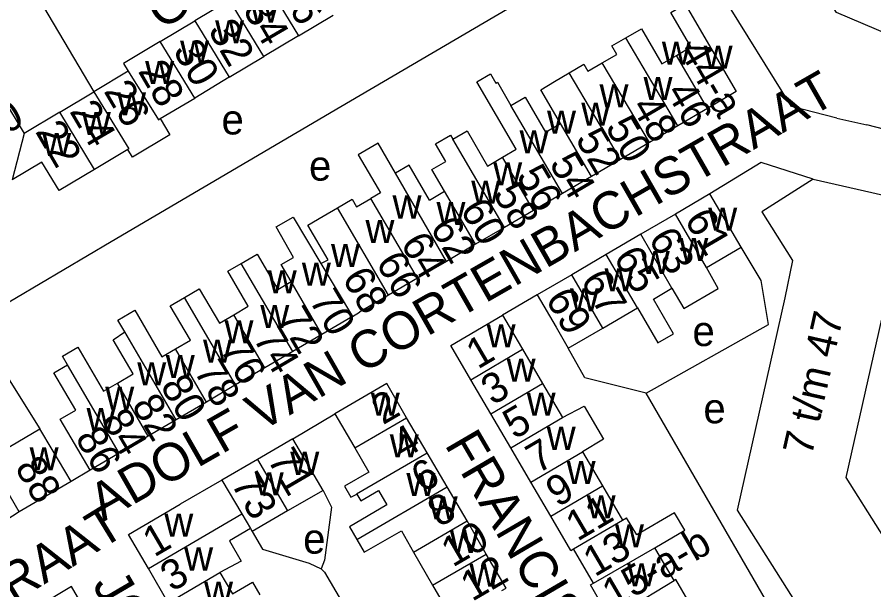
# Model space of a CAD drawing. Extents: x 161141 to 163125, y 381621 to 383200.
# Drawn here: x 162238.7 to 162353, y 382805.6 to 382882 of the extents above; entities that cross this region are included whole.
import ezdxf

# ---------------------------------------------------------------- set-up
doc = ezdxf.new("R2010")
doc.units = 0
for name, color, linetype in [('BLT_Basislijn', 7, 'Continuous'), ('BLT_Bebouwing', 7, 'Continuous'), ('BLT_Centroide', 7, 'Continuous'), ('BLT_Huisnummer', 7, 'Continuous'), ('BLT_Huisnummer_ tussenligend', 7, 'Continuous'), ('BLT_Huisnummer_reeks', 7, 'Continuous'), ('BLT_Onderverdeling_panden', 7, 'Continuous'), ('BLT_Straatnaam', 7, 'Continuous')]:
    doc.layers.add(name, color=color, linetype=linetype)

msp = doc.modelspace()

# ---------------------------------------------------------------- linework, layer by layer
at = {"layer": 'BLT_Basislijn'}
for p, q in [((162281.91, 382870.08), (162321.91, 382893.57)), ((162348.08, 382868.52), (162352.05, 382867.64)), ((162362.91, 382864.89), (162352.05, 382867.64)), ((162308.09, 382844.98), (162303.47, 382842.27)), ((162232.45, 382841.89), (162241.77, 382827.12)), ((162275.49, 382825.8), (162281.12, 382829.13)), ((162248.46, 382821.59), (162245.91, 382820.07)), ((162239.01, 382816.04), (162236.3, 382814.31))]:
    msp.add_line(p, q, dxfattribs=at)
for points in [[(162212.8, 382927.28), (162217.79, 382919.66), (162219.94, 382921.05), (162248.97, 382872.07)], [(162348.08, 382868.52), (162342.04, 382870.09), (162323.43, 382900), (162318.95, 382907.23), (162315.23, 382913.69)], [(162372.69, 382875.58), (162355.12, 382879.62), (162348.02, 382882.61), (162336.91, 382900), (162330.9, 382909.8)], [(162232.45, 382841.89), (162235.42, 382842.77), (162251.28, 382852.08), (162281.91, 382870.08)], [(162344.9, 382860.39), (162337.96, 382862.62), (162331.14, 382858.44)], [(162322.62, 382831.85), (162338.96, 382841.02), (162337.96, 382846.88), (162335.3, 382851.32)], [(162322.62, 382831.85), (162314.44, 382833.92), (162312.24, 382837.86)], [(162369.74, 382797.76), (162350.51, 382784.33), (162341.18, 382799.83), (162322.62, 382831.85)], [(162279.53, 382818.89), (162280.67, 382816.67), (162279.74, 382809.59), (162279.3, 382808.43)], [(162270.06, 382813.44), (162271.46, 382811.07), (162277.7, 382809.19), (162279.3, 382808.43)], [(162279.3, 382808.43), (162279.72, 382807.99), (162287.16, 382795.35), (162288.1, 382793.34), (162291.63, 382787.7), (162296.43, 382779.23), (162324.59, 382730.81)]]:
    msp.add_lwpolyline(points, dxfattribs=at)
at = {"layer": 'BLT_Bebouwing'}
for p, q in [((162267.04, 382884.3), (162262.43, 382881.53)), ((162276.26, 382879.51), (162280.88, 382882.27)), ((162257.82, 382878.76), (162262.43, 382881.53)), ((162276.26, 382879.51), (162271.64, 382876.75)), ((162267.02, 382873.99), (162271.64, 382876.75)), ((162253.52, 382874.8), (162248.97, 382872.07)), ((162267.02, 382873.99), (162262.41, 382871.23)), ((162244.4, 382869.32), (162248.97, 382872.07)), ((162236.75, 382871.31), (162239.66, 382866.48)), ((162257.82, 382868.5), (162262.41, 382871.23)), ((162330.81, 382869.83), (162326.84, 382867.51)), ((162244.4, 382869.32), (162239.66, 382866.48)), ((162326.84, 382867.51), (162323.08, 382865.3)), ((162323.08, 382865.3), (162319.21, 382863.04)), ((162253.51, 382864.37), (162249.04, 382861.7)), ((162319.21, 382863.04), (162315.34, 382860.78)), ((162315.34, 382860.78), (162311.48, 382858.51)), ((162311.48, 382858.51), (162307.61, 382856.24)), ((162331.14, 382858.44), (162326.53, 382855.75)), ((162307.61, 382856.24), (162303.74, 382853.98)), ((162326.53, 382855.75), (162321.92, 382853.06)), ((162303.74, 382853.98), (162299.88, 382851.72)), ((162321.92, 382853.06), (162317.31, 382850.36)), ((162299.88, 382851.72), (162296.01, 382849.45)), ((162330.69, 382848.63), (162335.3, 382851.32)), ((162317.31, 382850.36), (162312.7, 382847.67)), ((162296.01, 382849.45), (162292.15, 382847.19)), ((162292.15, 382847.19), (162288.28, 382844.92)), ((162312.7, 382847.67), (162308.09, 382844.98)), ((162288.28, 382844.92), (162284.41, 382842.66)), ((162283.44, 382842.08), (162284.41, 382842.66)), ((162316.86, 382840.55), (162321.47, 382843.24)), ((162283.44, 382842.08), (162279.39, 382839.71)), ((162251.53, 382838.98), (162253.1, 382840.03)), ((162312.24, 382837.86), (162316.86, 382840.55)), ((162279.39, 382839.71), (162275.5, 382837.43)), ((162306.14, 382837.72), (162308.81, 382833.16)), ((162275.5, 382837.43), (162271.76, 382835.24)), ((162271.76, 382835.24), (162267.87, 382832.97)), ((162301.9, 382829.11), (162299.24, 382833.67)), ((162308.81, 382833.16), (162311.48, 382828.61)), ((162267.87, 382832.97), (162263.99, 382830.69)), ((162263.99, 382830.69), (162259.95, 382828.33)), ((162293.41, 382823.93), (162290.68, 382828.6)), ((162304.57, 382824.56), (162301.9, 382829.11)), ((162259.95, 382828.33), (162256.22, 382826.14)), ((162256.22, 382826.14), (162252.34, 382823.87)), ((162275.49, 382825.8), (162270.77, 382823.04)), ((162252.34, 382823.87), (162248.46, 382821.59)), ((162296.07, 382819.38), (162293.41, 382823.93)), ((162307.24, 382820.01), (162304.57, 382824.56)), ((162314.14, 382824.05), (162316.81, 382819.5)), ((162270.77, 382823.04), (162266.05, 382820.29)), ((162245.91, 382820.07), (162239.01, 382816.04)), ((162266.05, 382820.29), (162260.49, 382817.05)), ((162298.74, 382814.85), (162296.07, 382819.38)), ((162309.91, 382815.45), (162307.24, 382820.01)), ((162316.81, 382819.5), (162319.48, 382814.95)), ((162279.53, 382818.89), (162274.8, 382816.16)), ((162274.8, 382816.16), (162270.06, 382813.44)), ((162301.3, 382810.42), (162298.74, 382814.85)), ((162312.58, 382810.9), (162309.91, 382815.45)), ((162319.48, 382814.95), (162320.01, 382815.26)), ((162321.4, 382812.96), (162320.01, 382815.26)), ((162269.84, 382813.81), (162270.06, 382813.44)), ((162291.58, 382810.67), (162294.15, 382806.26)), ((162303.95, 382805.87), (162301.3, 382810.42)), ((162312.58, 382810.9), (162312.93, 382811.11)), ((162315.6, 382806.55), (162312.93, 382811.11)), ((162326.37, 382806.89), (162323.79, 382811.23)), ((162258.88, 382803.92), (162256.23, 382808.47)), ((162294.15, 382806.26), (162296.8, 382801.71)), ((162303.4, 382805.55), (162303.95, 382805.87)), ((162315.2, 382806.32), (162315.6, 382806.55)), ((162317.86, 382801.76), (162315.2, 382806.32))]:
    msp.add_line(p, q, dxfattribs=at)
for points in [[(162326.67, 382876.91), (162328.61, 382878.05), (162325.92, 382882.64), (162327.85, 382883.73)], [(162327.85, 382883.73), (162334.66, 382872.09), (162330.81, 382869.83)], [(162319.94, 382879.27), (162322, 382880.47), (162324.74, 382875.78), (162326.67, 382876.91)], [(162257.82, 382878.76), (162252.91, 382875.83), (162253.52, 382874.8)], [(162316.76, 382875.91), (162318.72, 382877.04), (162318.07, 382878.17), (162319.94, 382879.27)], [(162312.37, 382874.59), (162314.32, 382875.73), (162314.87, 382874.79), (162316.76, 382875.91)], [(162303.47, 382863.32), (162305.3, 382864.39), (162300.04, 382873.38), (162301.85, 382874.45), (162302.57, 382873.22), (162302.79, 382873.34), (162304.59, 382870.22)], [(162311.2, 382867.85), (162308.57, 382872.33), (162310.41, 382873.44), (162312.37, 382874.59)], [(162304.59, 382870.22), (162306.49, 382871.34), (162309.21, 382866.68), (162311.2, 382867.85)], [(162257.82, 382868.5), (162259.11, 382866.33), (162254.11, 382863.36), (162253.51, 382864.37)], [(162295.73, 382858.8), (162294.04, 382861.69), (162295.9, 382862.78), (162294.53, 382865.11), (162296.54, 382866.28), (162296.86, 382865.73)], [(162296.86, 382865.73), (162298.76, 382866.84), (162301.49, 382862.16), (162303.47, 382863.32)], [(162289.21, 382861.22), (162286.88, 382865.19), (162284.22, 382863.64), (162286.87, 382859.12), (162287.19, 382858.57), (162285.91, 382857.83)], [(162249.04, 382861.7), (162244.34, 382858.88), (162242.01, 382862.69), (162238.06, 382860.31)], [(162293.73, 382857.62), (162291.01, 382862.27), (162289.21, 382861.22)], [(162344.9, 382860.39), (162338.05, 382856.06), (162342.15, 382849.54), (162341.14, 382844.6), (162334.78, 382816.27)], [(162344.9, 382860.39), (162361.15, 382856.7), (162361.15, 382856.7)], [(162293.73, 382857.62), (162295.73, 382858.8)], [(162335.3, 382851.32), (162333.66, 382854.12), (162331.14, 382858.44)], [(162281.45, 382856.59), (162283.4, 382857.73), (162284, 382856.7), (162285.91, 382857.83)], [(162279.24, 382849.16), (162280.22, 382849.65), (162277.51, 382854.28), (162279.53, 382855.46), (162281.45, 382856.59)], [(162381.56, 382852.12), (162380.23, 382846.22), (162383.74, 382845.43), (162376.75, 382814.45), (162362.5, 382805.44), (162358.29, 382806.4), (162349.3, 382820.62), (162356.31, 382851.62), (162359.83, 382850.83), (162361.15, 382856.7)], [(162275.26, 382846.75), (162273.93, 382849.02), (162275.57, 382849.98), (162273.26, 382854.04), (162275.56, 382855.35), (162279.24, 382849.16)], [(162268.62, 382849.18), (162270.73, 382850.41), (162273.48, 382845.71), (162275.26, 382846.75)], [(162267.61, 382842.31), (162269.55, 382843.45), (162266.82, 382848.12), (162268.62, 382849.18)], [(162326.08, 382845.86), (162327.66, 382843.16), (162332.22, 382845.82), (162330.69, 382848.63)], [(162334.78, 382816.27), (162352.31, 382788.59), (162381.03, 382806.89), (162388.22, 382805.26), (162394.4, 382832.58), (162398.03, 382848.41)], [(162261.04, 382844.63), (162263.02, 382845.79), (162265.71, 382841.2), (162267.61, 382842.31)], [(162321.47, 382843.24), (162324.21, 382838.59), (162326.29, 382839.8), (162323.6, 382844.41), (162326.08, 382845.86)], [(162259.84, 382837.78), (162261.84, 382838.95), (162259.15, 382843.53), (162261.04, 382844.63)], [(162308.09, 382844.98), (162310.61, 382840.66), (162312.24, 382837.86)], [(162253.1, 382840.03), (162252.17, 382841.61), (162254.41, 382842.92)], [(162254.41, 382842.92), (162258.04, 382836.73), (162259.84, 382837.78)], [(162299.24, 382833.67), (162296.57, 382838.22), (162303.47, 382842.27)], [(162303.47, 382842.27), (162306, 382837.95), (162306.14, 382837.72)], [(162252.1, 382833.22), (162254.18, 382834.44), (162251.53, 382838.98)], [(162245.44, 382835.65), (162244.76, 382836.8), (162246.82, 382838.01), (162250.26, 382832.14), (162252.1, 382833.22)], [(162244.46, 382828.39), (162246.56, 382829.62), (162243.64, 382834.6), (162245.44, 382835.65)], [(162290.68, 382828.6), (162288.02, 382833.16), (162281.12, 382829.13)], [(162311.48, 382828.61), (162314.38, 382830.12), (162316.96, 382825.74), (162314.14, 382824.05)], [(162281.12, 382829.13), (162283.64, 382824.81), (162283.77, 382824.58)], [(162248.46, 382821.59), (162245.93, 382825.91), (162244.46, 382828.39)], [(162239.01, 382816.04), (162236.49, 382820.36), (162234.88, 382823.09), (162241.77, 382827.12)], [(162245.91, 382820.07), (162243.38, 382824.38), (162241.77, 382827.12)], [(162279.53, 382818.89), (162278.02, 382821.49), (162275.49, 382825.8)], [(162283.77, 382824.58), (162285.66, 382821.35), (162282.41, 382819.46), (162283.26, 382818.01), (162284.04, 382818.4)], [(162284.04, 382818.4), (162284.55, 382817.52), (162286.91, 382818.9), (162288.04, 382816.96), (162283.07, 382814.05), (162284.05, 382812.37)], [(162256.23, 382808.47), (162253.58, 382813.03), (162260.49, 382817.05)], [(162323.79, 382811.23), (162327.8, 382813.58), (162326.43, 382815.92), (162321.4, 382812.97)], [(162269.84, 382813.81), (162267.04, 382812.17), (162268.63, 382809.46), (162265.78, 382807.96)], [(162284.05, 382812.37), (162285.03, 382810.68), (162290, 382813.5), (162291.58, 382810.67)], [(162265.78, 382807.96), (162267.44, 382805.09), (162270.12, 382806.65), (162271.09, 382804.96)], [(162329.32, 382802.35), (162326.58, 382807.02), (162326.37, 382806.89)], [(162250.78, 382797.8), (162245.97, 382806.08), (162241.38, 382803.35)]]:
    msp.add_lwpolyline(points, dxfattribs=at)
at = {"layer": 'BLT_Onderverdeling_panden'}
for p, q in [((162271.66, 382887.07), (162276.26, 382879.51)), ((162271.64, 382876.75), (162267.04, 382884.3)), ((162262.43, 382881.53), (162267.02, 382873.99)), ((162262.41, 382871.23), (162257.82, 382878.76)), ((162326.84, 382867.51), (162319.94, 382879.27)), ((162330.81, 382869.83), (162326.67, 382876.91)), ((162323.08, 382865.3), (162316.76, 382875.91)), ((162319.21, 382863.04), (162312.37, 382874.59)), ((162311.48, 382858.51), (162304.59, 382870.22)), ((162249.04, 382861.7), (162244.4, 382869.32)), ((162315.34, 382860.78), (162311.2, 382867.85)), ((162239.66, 382866.48), (162238.06, 382860.31)), ((162303.74, 382853.98), (162296.86, 382865.73)), ((162307.61, 382856.24), (162303.47, 382863.32)), ((162296.01, 382849.45), (162289.21, 382861.22)), ((162299.88, 382851.72), (162295.73, 382858.8)), ((162292.15, 382847.19), (162285.91, 382857.83)), ((162288.28, 382844.92), (162281.45, 382856.59)), ((162330.69, 382848.63), (162326.53, 382855.75)), ((162326.08, 382845.86), (162321.92, 382853.06)), ((162321.47, 382843.24), (162317.31, 382850.36)), ((162275.5, 382837.43), (162268.62, 382849.18)), ((162279.24, 382849.16), (162283.44, 382842.08)), ((162279.39, 382839.71), (162275.26, 382846.75)), ((162316.86, 382840.55), (162312.7, 382847.67)), ((162267.87, 382832.97), (162261.04, 382844.63)), ((162271.76, 382835.24), (162267.61, 382842.31)), ((162259.95, 382828.33), (162253.1, 382840.03)), ((162263.99, 382830.69), (162259.84, 382837.78)), ((162299.24, 382833.67), (162306.14, 382837.72)), ((162252.34, 382823.87), (162245.44, 382835.65)), ((162256.22, 382826.14), (162252.1, 382833.22)), ((162301.9, 382829.11), (162308.81, 382833.16)), ((162283.77, 382824.58), (162290.68, 382828.6)), ((162304.57, 382824.56), (162311.48, 382828.61)), ((162307.24, 382820.01), (162314.14, 382824.05)), ((162270.77, 382823.04), (162274.8, 382816.16)), ((162284.05, 382812.37), (162296.07, 382819.38)), ((162309.91, 382815.45), (162316.81, 382819.5)), ((162256.23, 382808.47), (162268.7, 382815.77)), ((162268.7, 382815.77), (162269.84, 382813.81)), ((162291.58, 382810.67), (162298.74, 382814.85)), ((162312.93, 382811.11), (162319.48, 382814.95)), ((162294.15, 382806.26), (162301.3, 382810.42)), ((162258.88, 382803.92), (162265.78, 382807.96)), ((162317.86, 382801.76), (162326.37, 382806.89))]:
    msp.add_line(p, q, dxfattribs=at)
for points in [[(162253.52, 382874.8), (162257.56, 382868.34), (162257.82, 382868.5)], [(162248.97, 382872.07), (162253.62, 382864.44), (162253.51, 382864.37)], [(162284.04, 382818.4), (162284.01, 382818.45), (162293.41, 382823.93)], [(162266.05, 382820.29), (162268.7, 382815.77)], [(162315.6, 382806.55), (162323.79, 382811.23)]]:
    msp.add_lwpolyline(points, dxfattribs=at)

# ---------------------------------------------------------------- texts
at = {"layer": 'BLT_Centroide'}
for s, p in [('w', (162269.78, 382881.27)), ('w', (162265.13, 382878.53)), ('w', (162260.46, 382875.81)), ('w', (162324.73, 382875.66)), ('w', (162330.3, 382875.14)), ('w', (162255.8, 382873.08)), ('w', (162316.41, 382869.98)), ('w', (162322.28, 382870.97)), ('w', (162252.06, 382868.93)), ('w', (162313.98, 382867.53)), ('w', (162247.36, 382866.31)), ('e', (162265.99, 382866.37)), ('w', (162309.41, 382866.47)), ('w', (162242.07, 382863.51)), ('w', (162305.75, 382863.84)), ('e', (162277.66, 382860.21)), ('w', (162302.23, 382859.58)), ('w', (162299.3, 382857.12)), ('w', (162288.8, 382855.16)), ('w', (162294.66, 382854.31)), ('w', (162330.91, 382853.53)), ('w', (162285.19, 382851.89)), ('w', (162327.06, 382849.5)), ('w', (162280.59, 382848.7)), ('w', (162321.92, 382847.77)), ('w', (162276.71, 382846.19)), ('w', (162272.16, 382845.19)), ('w', (162317.08, 382845.45)), ('w', (162312.47, 382842.77)), ('w', (162271.16, 382840.55)), ('w', (162266.39, 382838.53)), ('w', (162301.35, 382837.97)), ('e', (162328.81, 382838.15)), ('w', (162263.52, 382835.95)), ('w', (162258.55, 382833.88)), ('w', (162304.02, 382833.41)), ('w', (162254.75, 382832.92)), ('w', (162250.48, 382829.66)), ('w', (162285.9, 382828.88)), ('w', (162306.69, 382828.88)), ('e', (162330.27, 382827.85)), ('w', (162247.98, 382826.83)), ('w', (162309.36, 382824.31)), ('w', (162288.43, 382823.31)), ('w', (162240.39, 382821.58)), ('w', (162275.16, 382820.98)), ('w', (162312.02, 382819.75)), ('w', (162270.42, 382818.25)), ('w', (162290.65, 382818.16)), ('w', (162314.7, 382815.19)), ('w', (162293.62, 382815.03)), ('w', (162258.36, 382812.75)), ('e', (162276.88, 382810.47)), ('w', (162296.43, 382810.56)), ('w', (162318.47, 382811.31)), ('w', (162261, 382808.22)), ('w', (162299.05, 382806.06)), ('w', (162320.09, 382806.12)), ('w', (162263.66, 382803.66))]:
    msp.add_text(s, height=4, dxfattribs=at).set_placement(p)
at = {"layer": 'BLT_Huisnummer'}
for s, rotation, p in [('34', 300.3592, (162268.76, 382883.01)), ('30', 300.3592, (162259.44, 382877.55)), ('26', 300.3592, (162250.21, 382872.15)), ('48', 300.3634, (162320.58, 382870.09)), ('22', 300.3592, (162241.07, 382866.77)), ('52', 300.3606, (162313.11, 382865.78)), ('56', 300.3631, (162305.22, 382860.85)), ('60', 300.36, (162297.74, 382856.35)), ('61', 300.2844, (162327.66, 382855.03)), ('64', 300.3606, (162289.79, 382851.84)), ('65', 300.2844, (162318.2, 382849.99)), ('68', 300.3645, (162282, 382847.21)), ('69', 300.2857, (162309.12, 382844.44)), ('72', 300.3601, (162273.43, 382841.93)), ('76', 300.3609, (162265.7, 382837.77)), ('1', 30.3962, (162300.17, 382834.99)), ('80', 300.3602, (162257.75, 382832.85)), ('2', 30.1977, (162287.52, 382827.58)), ('84', 300.3604, (162249.86, 382828.3)), ('5', 30.3921, (162305.06, 382825.64)), ('71', 300.3066, (162272.03, 382823.04)), ('88', 300.3703, (162238.34, 382821.97)), ('6', 30.1988, (162292.82, 382818.49)), ('73', 300.293, (162267.18, 382819.82)), ('9', 30.3948, (162310.8, 382816.59)), ('1', 30.3168, (162257.01, 382809.93)), ('10', 30.1973, (162296.83, 382808.59)), ('13', 30.3945, (162315.78, 382807.3))]:
    msp.add_text(s, height=4, rotation=rotation, dxfattribs=at).set_placement(p)
at = {"layer": 'BLT_Huisnummer_ tussenligend'}
for s, rotation, p in [('36', 300.3592, (162273.42, 382885.74)), ('32', 300.3592, (162264.11, 382880.26)), ('28', 300.3592, (162254.78, 382874.82)), ('46', 300.3592, (162325.21, 382872.02)), ('20', 30.3592, (162234.78, 382864.83)), ('24', 300.3592, (162245.64, 382869.47)), ('50', 300.3634, (162317.1, 382867.35)), ('54', 300.3606, (162309.63, 382862.5)), ('58', 300.3631, (162302.12, 382858.46)), ('62', 300.36, (162293.73, 382853.96)), ('63', 300.2844, (162322.86, 382852.49)), ('66', 300.3606, (162286.5, 382849.28)), ('67', 300.2844, (162313.8, 382846.89)), ('70', 300.3645, (162277.61, 382844.29)), ('74', 300.3601, (162270.13, 382839.2)), ('78', 300.3609, (162262.23, 382834.84)), ('3', 30.3962, (162302.16, 382830.18)), ('82', 300.3602, (162253.92, 382830.28)), ('86', 300.3604, (162246.39, 382825.92)), ('4', 30.1977, (162290.25, 382823)), ('7', 30.3921, (162308.15, 382821.06)), ('8', 30.1988, (162295.02, 382813.91)), ('11', 30.3948, (162313.46, 382812.05)), ('3', 30.3168, (162259.37, 382805.31)), ('12', 30.1973, (162299.41, 382804.02))]:
    msp.add_text(s, height=4, rotation=rotation, dxfattribs=at).set_placement(p)
at = {"layer": 'BLT_Huisnummer_reeks'}
for s, rotation, p in [('44-a', 300.3592, (162326.94, 382877.55)), ('7 t/m 47', 77.249, (162344.71, 382823.37)), ('15-a-b', 30.3945, (162318.31, 382803.03))]:
    msp.add_text(s, height=4, rotation=rotation, dxfattribs=at).set_placement(p)
at = {"layer": 'BLT_Straatnaam'}
for s, rotation, p in [('GULDENSTRAAT', 30.6959, (162257.85, 382880.22)), ('ADOLF VAN CORTENBACHSTRAAT', 29.7641, (162250.2, 382814.67)), ('FRANCISCUS SONNIUSSTRAAT', 300.2664, (162295.67, 382825.02)), ('ADOLF VAN CORTENBACHSTRAAT', 31.5065, (162157.12, 382754.11)), ('JOHANNES VAN EINDHOVENSTRAAT', 300.37, (162248.67, 382806.32))]:
    msp.add_text(s, height=5, rotation=rotation, dxfattribs=at).set_placement(p)

doc.saveas('drawing.dxf')
